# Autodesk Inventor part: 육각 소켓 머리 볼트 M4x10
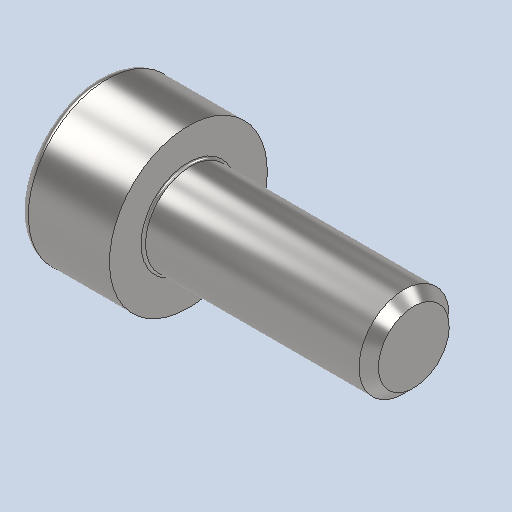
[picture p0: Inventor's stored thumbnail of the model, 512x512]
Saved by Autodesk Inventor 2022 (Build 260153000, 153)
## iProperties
Created: 2024-11
Part Number: 육각 소켓 머리 볼트 M4x10
Material: 강철, 연강
Description: 6각머리 태핑 나사
Document SubType Name: Modeling
Designer: PC-12
Density: 7.85 g/cm^3
Appearance: 기본값
Author: jhkim
Sending System: Autodesk Inventor 2025
Preprocessor: ST-DEVELOPER v20
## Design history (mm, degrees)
node "육각 소켓 머리 볼트 M4x101"
node "솔리드1"
body "Solid1"
